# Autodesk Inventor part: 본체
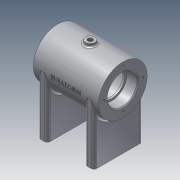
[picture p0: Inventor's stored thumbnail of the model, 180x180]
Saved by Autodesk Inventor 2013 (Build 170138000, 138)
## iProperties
Created: 2020-07
Part Number: 본체
Material: 알루미늄 6061
Document SubType Name: Modeling
Designer: 88
Mass: 306.379 g
Surface Area: 357.563 cm^2
Volume: 113.055 cm^3
Density: 2.71 g/cm^3
Author: 88
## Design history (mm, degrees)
sketch "스케치2"
  geometry: C1 r 26 at (0, 0); 1 further point
  constraints: 1 centre point, 1 coincident
  dimensions: "d0" = 52 diameter of C1
extrude "돌출1" new body sketch "스케치2" stored distance "d1" = 70; taper "d2" = 0 deg
node "작업 평면2"
  node "작업 평면1"
sketch "스케치3"
  geometry: C1 r 5 at (0, 0); 1 further point
  constraints: 1 centre point, 1 coincident
  dimensions: "d4" = 10 diameter of C1
extrude "돌출2" join sketch "스케치3" stored distance "d5" = 70; taper "d6" = 0 deg
sketch "스케치4"
  geometry: L1 (35, -26)-(-35, -26) reference; L2 (-35, -26)-(-35, 26) reference; L3 (-35, 26)-(-5, 26) reference; L4 (-5, 26)-(-5, 29) reference; L5 (-5, 29)-(5, 29) reference; L6 (5, 29)-(5, 26) reference; L7 (5, 26)-(35, 26) reference; L8 (35, 26)-(35, -26) reference; L9 (-35, 0)-(35, 0); L10 (-35, 0)-(-35, 16); L11 (-35, 16)-(-23, 16); L12 (-23, 16)-(-23, 14); L13 (-23, 14)-(-21, 14); L14 (-21, 14)-(-21, 21); L15 (-21, 21)-(21, 21); L16 (21, 21)-(21, 14); L17 (21, 14)-(23, 14); L18 (23, 14)-(23, 16); L19 (23, 16)-(35, 16); L20 (35, 16)-(35, 0); 1 further point
  constraints: 24 end point, 6 parallel, 3 perpendicular, 2 midpoint, 2 point on line, 1 collinear
  dimensions: "d7" = 32 diameter of L11 L9; "d9" = 28 diameter of L13 L9; "d10" = 42 diameter of L15 L9; "d11" = 28 diameter of L17 L9; "d12" = 32 diameter of L19 L9; "d13" = 12 distance of L10.end L11.end; "d14" = 42 distance of L14.end L15.end; "d15" = 12 distance of L18.end L19.end; "d16" = 2 distance of L12.end L13.end; "d17" = 2 distance of L16.end L17.end (derived)
revolve "회전1" sketch "스케치4" stored, may be unused: angle "d18" = 90 deg
node "작업 평면3"
sketch "스케치5"
  geometry: L1 (0, 26)-(64, 26); L2 (64, 26)-(64, -26); L3 (64, -26)-(0, -26); C1 r 21 at (0, 0) reference; A1 r 26 centre (0, 0) between (0, 26) and (0, -26) reference; 1 further point
  constraints: 6 end point, 2 horizontal, 2 point on circle, 2 tangent, 1 perpendicular
  dimensions: "d20" = 64 distance of L1.start L1.end
extrude "돌출3" join sketch "스케치5" distance "d22" = 10; taper "d23" = 0 deg
sketch "스케치6"
  geometry: L1 (-10, 0)-(-10, 52) reference; L2 (50, 0)-(50, 52) reference; 5 further points
  constraints: 2 horizontal alignment, 2 vertical alignment
  dimensions: "d24" = 5 distance from line of L1 point (-5, 46); "d25" = 5 distance from line of L2 point (45, 46); "d26" = 40 distance of point (-5, 6) point (-5, 46); "d27" = 20 vertical distance of point (20, 26) point (-5, 46)
hole "구멍1" sketch "스케치6" at (-5, 46), (-5, 6), (45, 46), (45, 6) diameter "d28" = 4.134; stored, may be unused: countersink angle "d32" = 90 deg, drill point angle "d34" = 118 deg; dims "d29" = 8, "d30" = 4, "d31" = 2, "d33" = 10
fillet "모깎기1" dims "d35" = 3
fillet "모깎기2" dims "d36" = 0.3
chamfer "모따기1" distance "d37" = 1; stored, may be unused: second distance "d38" = 2, angle "d39" = 45 deg
fillet "모깎기3" dims "d40" = 3
fillet "모깎기4" dims "d41" = 3
node "작업 평면5"
  node "작업 평면4"
sketch "스케치7"
  geometry: C1 r 6 at (0, 0); 1 further point
  constraints: 1 centre point, 1 coincident
  dimensions: "d44" = 12 diameter of C1
extrude "돌출4" join sketch "스케치7" stored distance "d45" = 10; taper "d46" = 0 deg
sketch "스케치8"
  geometry: C1 r 6 at (0, 0) reference; 1 further point
  constraints: 1 coincident
hole "구멍2" sketch "스케치8" at (0, 0) diameter "d47" = 5.188; stored, may be unused: countersink angle "d51" = 90 deg, drill point angle "d53" = 118 deg; dims "d48" = 8, "d49" = 4, "d50" = 2, "d52" = 16.75
sketch "스케치9"
  geometry: A1 r 5 centre (0, 0) between (-5, 0) and (-5, 0) reference; 1 further point
  constraints: 1 coincident
hole "구멍3" sketch "스케치9" at (0, 0) diameter "d54" = 5.188; stored, may be unused: countersink angle "d58" = 90 deg, drill point angle "d60" = 118 deg; dims "d55" = 8, "d56" = 4, "d57" = 2, "d59" = 16.75
fillet "모깎기5" dims "d61" = 2
sketch "스케치10" dims "d63" = 42
  geometry: 3 further points
  constraints: 2 vertical alignment, 1 coincident, 2 other
hole "구멍4" sketch "스케치10" at (0, 21) diameter "d64" = 3.242; stored, may be unused: countersink angle "d68" = 90 deg, drill point angle "d70" = 118 deg; dims "d65" = 8, "d66" = 4, "d67" = 2, "d69" = 10
node "작업 평면6"
sketch "스케치11"
  geometry: L1 (-35, 26)-(-35, -26) reference; 2 further points
  constraints: 1 other
  dimensions: "d75" = 35 distance from line of point (0, 0) L1; "d76" = 26 vertical distance of L1.start point (0, 0)
feature "엠보싱1" sketch "스케치11" dims "d7" = 32, "d9" = 28, "d10" = 42, "d11" = 28, "d12" = 32, "d13" = 12, "d14" = 42, "d15" = 12, "d16" = 2, "d17" = 2 (derived), "d77" = 0.5, "d78" = 0
node "솔리드1"
mirror "대칭1"
pattern_circular "원형 패턴1" dims angle "d72" = 360 deg
mirror "대칭2"
node "절단 모서리 투영1"
node "절단 모서리 투영2"
other parameters: "d3" = 3, "d42" = 20 deg, "d43" = -29, "d74" = 43.5
